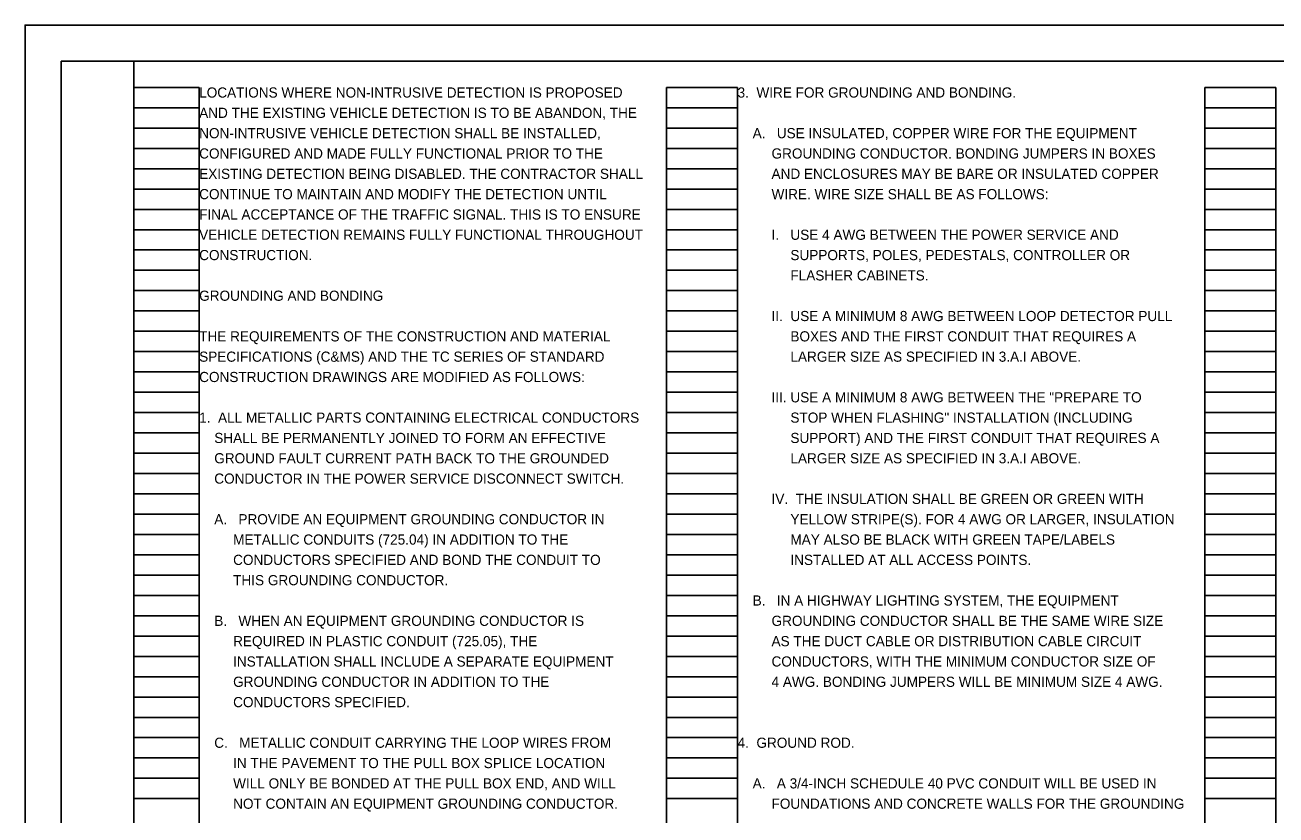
# Model space of a CAD drawing. Extents: x 0 to 44.9, y 0 to 22.
# Drawn here: x 0 to 17.24, y 11.11 to 22 of the extents above; entities that cross this region are included whole.
import ezdxf

# ---------------------------------------------------------------- set-up
doc = ezdxf.new("R2010")
doc.units = 0
for name, color, linetype in [('SH_Border', 7, 'Continuous'), ('SH_Cut_Line', 7, 'Continuous'), ('SH_Data', 7, 'Continuous'), ('SH_Text', 7, 'Continuous')]:
    doc.layers.add(name, color=color, linetype=linetype)

msp = doc.modelspace()

# ---------------------------------------------------------------- linework, layer by layer
at = {"layer": 'SH_Border'}
for points in [[(0.5, 21.5), (1.5, 21.5), (1.5, 0.5), (0.5, 0.5)], [(1.5, 21.5), (33.5, 21.5), (33.5, 0.5), (1.5, 0.5)]]:
    msp.add_lwpolyline(points, close=True, dxfattribs=at)
at = {"layer": 'SH_Cut_Line'}
msp.add_lwpolyline([(0, 0), (34, 0), (34, 22), (0, 22)], close=True, dxfattribs=at)
at = {"layer": 'SH_Data'}
for p, q in [((1.5, 0.98), (1.5, 21.14)), ((1.5, 21.14), (2.4, 21.14)), ((2.4, 0.98), (2.4, 21.14)), ((8.84, 0.98), (8.84, 21.14)), ((8.84, 21.14), (9.82, 21.14)), ((9.82, 0.98), (9.82, 21.14)), ((16.26, 0.98), (16.26, 21.14)), ((16.26, 21.14), (17.24, 21.14)), ((17.24, 0.98), (17.24, 21.14)), ((1.5, 20.86), (2.4, 20.86)), ((8.84, 20.86), (9.82, 20.86)), ((16.26, 20.86), (17.24, 20.86)), ((1.5, 20.58), (2.4, 20.58)), ((8.84, 20.58), (9.82, 20.58)), ((16.26, 20.58), (17.24, 20.58)), ((1.5, 20.3), (2.4, 20.3)), ((8.84, 20.3), (9.82, 20.3)), ((16.26, 20.3), (17.24, 20.3)), ((1.5, 20.02), (2.4, 20.02)), ((8.84, 20.02), (9.82, 20.02)), ((16.26, 20.02), (17.24, 20.02)), ((1.5, 19.74), (2.4, 19.74)), ((8.84, 19.74), (9.82, 19.74)), ((16.26, 19.74), (17.24, 19.74)), ((1.5, 19.46), (2.4, 19.46)), ((8.84, 19.46), (9.82, 19.46)), ((16.26, 19.46), (17.24, 19.46)), ((1.5, 19.18), (2.4, 19.18)), ((8.84, 19.18), (9.82, 19.18)), ((16.26, 19.18), (17.24, 19.18)), ((1.5, 18.9), (2.4, 18.9)), ((8.84, 18.9), (9.82, 18.9)), ((16.26, 18.9), (17.24, 18.9)), ((1.5, 18.62), (2.4, 18.62)), ((8.84, 18.62), (9.82, 18.62)), ((16.26, 18.62), (17.24, 18.62)), ((1.5, 18.34), (2.4, 18.34)), ((8.84, 18.34), (9.82, 18.34)), ((16.26, 18.34), (17.24, 18.34)), ((1.5, 18.06), (2.4, 18.06)), ((8.84, 18.06), (9.82, 18.06)), ((16.26, 18.06), (17.24, 18.06)), ((1.5, 17.78), (2.4, 17.78)), ((8.84, 17.78), (9.82, 17.78)), ((16.26, 17.78), (17.24, 17.78)), ((1.5, 17.5), (2.4, 17.5)), ((8.84, 17.5), (9.82, 17.5)), ((16.26, 17.5), (17.24, 17.5)), ((1.5, 17.22), (2.4, 17.22)), ((8.84, 17.22), (9.82, 17.22)), ((16.26, 17.22), (17.24, 17.22)), ((1.5, 16.94), (2.4, 16.94)), ((8.84, 16.94), (9.82, 16.94)), ((16.26, 16.94), (17.24, 16.94)), ((1.5, 16.66), (2.4, 16.66)), ((8.84, 16.66), (9.82, 16.66)), ((16.26, 16.66), (17.24, 16.66)), ((1.5, 16.38), (2.4, 16.38)), ((8.84, 16.38), (9.82, 16.38)), ((16.26, 16.38), (17.24, 16.38)), ((1.5, 16.1), (2.4, 16.1)), ((8.84, 16.1), (9.82, 16.1)), ((16.26, 16.1), (17.24, 16.1)), ((1.5, 15.82), (2.4, 15.82)), ((8.84, 15.82), (9.82, 15.82)), ((16.26, 15.82), (17.24, 15.82)), ((1.5, 15.54), (2.4, 15.54)), ((8.84, 15.54), (9.82, 15.54)), ((16.26, 15.54), (17.24, 15.54)), ((1.5, 15.26), (2.4, 15.26)), ((8.84, 15.26), (9.82, 15.26)), ((16.26, 15.26), (17.24, 15.26)), ((1.5, 14.98), (2.4, 14.98)), ((8.84, 14.98), (9.82, 14.98)), ((16.26, 14.98), (17.24, 14.98)), ((1.5, 14.7), (2.4, 14.7)), ((8.84, 14.7), (9.82, 14.7)), ((16.26, 14.7), (17.24, 14.7)), ((1.5, 14.42), (2.4, 14.42)), ((8.84, 14.42), (9.82, 14.42)), ((16.26, 14.42), (17.24, 14.42)), ((1.5, 14.14), (2.4, 14.14)), ((8.84, 14.14), (9.82, 14.14)), ((16.26, 14.14), (17.24, 14.14)), ((1.5, 13.86), (2.4, 13.86)), ((8.84, 13.86), (9.82, 13.86)), ((16.26, 13.86), (17.24, 13.86)), ((1.5, 13.58), (2.4, 13.58)), ((8.84, 13.58), (9.82, 13.58)), ((16.26, 13.58), (17.24, 13.58)), ((1.5, 13.3), (2.4, 13.3)), ((8.84, 13.3), (9.82, 13.3)), ((16.26, 13.3), (17.24, 13.3)), ((1.5, 13.02), (2.4, 13.02)), ((8.84, 13.02), (9.82, 13.02)), ((16.26, 13.02), (17.24, 13.02)), ((1.5, 12.74), (2.4, 12.74)), ((8.84, 12.74), (9.82, 12.74)), ((16.26, 12.74), (17.24, 12.74)), ((1.5, 12.46), (2.4, 12.46)), ((8.84, 12.46), (9.82, 12.46)), ((16.26, 12.46), (17.24, 12.46)), ((1.5, 12.18), (2.4, 12.18)), ((8.84, 12.18), (9.82, 12.18)), ((16.26, 12.18), (17.24, 12.18)), ((1.5, 11.9), (2.4, 11.9)), ((8.84, 11.9), (9.82, 11.9)), ((16.26, 11.9), (17.24, 11.9)), ((1.5, 11.62), (2.4, 11.62)), ((8.84, 11.62), (9.82, 11.62)), ((16.26, 11.62), (17.24, 11.62)), ((1.5, 11.34), (2.4, 11.34)), ((8.84, 11.34), (9.82, 11.34)), ((16.26, 11.34), (17.24, 11.34))]:
    msp.add_line(p, q, dxfattribs=at)

# ---------------------------------------------------------------- texts
at = {"layer": 'SH_Text'}
for s, p in [('LOCATIONS WHERE NON-INTRUSIVE DETECTION IS PROPOSED', (2.4, 21)), ('3.  WIRE FOR GROUNDING AND BONDING.', (9.82, 21)), ('AND THE EXISTING VEHICLE DETECTION IS TO BE ABANDON, THE', (2.4, 20.72)), ('NON-INTRUSIVE VEHICLE DETECTION SHALL BE INSTALLED,', (2.4, 20.44)), ('    A.   USE INSULATED, COPPER WIRE FOR THE EQUIPMENT', (9.82, 20.44)), ('CONFIGURED AND MADE FULLY FUNCTIONAL PRIOR TO THE', (2.4, 20.16)), ('         GROUNDING CONDUCTOR. BONDING JUMPERS IN BOXES', (9.82, 20.16)), ('EXISTING DETECTION BEING DISABLED. THE CONTRACTOR SHALL', (2.4, 19.88)), ('         AND ENCLOSURES MAY BE BARE OR INSULATED COPPER', (9.82, 19.88)), ('CONTINUE TO MAINTAIN AND MODIFY THE DETECTION UNTIL', (2.4, 19.6)), ('         WIRE. WIRE SIZE SHALL BE AS FOLLOWS:', (9.82, 19.6)), ('FINAL ACCEPTANCE OF THE TRAFFIC SIGNAL. THIS IS TO ENSURE', (2.4, 19.32)), ('VEHICLE DETECTION REMAINS FULLY FUNCTIONAL THROUGHOUT', (2.4, 19.04)), ('         I.   USE 4 AWG BETWEEN THE POWER SERVICE AND', (9.82, 19.04)), ('CONSTRUCTION.', (2.4, 18.76)), ('              SUPPORTS, POLES, PEDESTALS, CONTROLLER OR', (9.82, 18.76)), ('              FLASHER CABINETS.', (9.82, 18.48)), ('GROUNDING AND BONDING', (2.4, 18.2)), ('         II.  USE A MINIMUM 8 AWG BETWEEN LOOP DETECTOR PULL', (9.82, 17.92)), ('THE REQUIREMENTS OF THE CONSTRUCTION AND MATERIAL', (2.4, 17.64)), ('              BOXES AND THE FIRST CONDUIT THAT REQUIRES A', (9.82, 17.64)), ('SPECIFICATIONS (C&MS) AND THE TC SERIES OF STANDARD', (2.4, 17.36)), ('              LARGER SIZE AS SPECIFIED IN 3.A.I ABOVE.', (9.82, 17.36)), ('CONSTRUCTION DRAWINGS ARE MODIFIED AS FOLLOWS:', (2.4, 17.08)), ('         III. USE A MINIMUM 8 AWG BETWEEN THE "PREPARE TO', (9.82, 16.8)), ('1.  ALL METALLIC PARTS CONTAINING ELECTRICAL CONDUCTORS', (2.4, 16.52)), ('              STOP WHEN FLASHING" INSTALLATION (INCLUDING', (9.82, 16.52)), ('    SHALL BE PERMANENTLY JOINED TO FORM AN EFFECTIVE', (2.4, 16.24)), ('              SUPPORT) AND THE FIRST CONDUIT THAT REQUIRES A', (9.82, 16.24)), ('    GROUND FAULT CURRENT PATH BACK TO THE GROUNDED', (2.4, 15.96)), ('              LARGER SIZE AS SPECIFIED IN 3.A.I ABOVE.', (9.82, 15.96)), ('    CONDUCTOR IN THE POWER SERVICE DISCONNECT SWITCH.', (2.4, 15.68)), ('         IV.  THE INSULATION SHALL BE GREEN OR GREEN WITH', (9.82, 15.4)), ('    A.   PROVIDE AN EQUIPMENT GROUNDING CONDUCTOR IN', (2.4, 15.12)), ('              YELLOW STRIPE(S). FOR 4 AWG OR LARGER, INSULATION', (9.82, 15.12)), ('         METALLIC CONDUITS (725.04) IN ADDITION TO THE', (2.4, 14.84)), ('              MAY ALSO BE BLACK WITH GREEN TAPE/LABELS', (9.82, 14.84)), ('         CONDUCTORS SPECIFIED AND BOND THE CONDUIT TO', (2.4, 14.56)), ('              INSTALLED AT ALL ACCESS POINTS.', (9.82, 14.56)), ('         THIS GROUNDING CONDUCTOR.', (2.4, 14.28)), ('    B.   IN A HIGHWAY LIGHTING SYSTEM, THE EQUIPMENT', (9.82, 14)), ('    B.   WHEN AN EQUIPMENT GROUNDING CONDUCTOR IS', (2.4, 13.72)), ('         GROUNDING CONDUCTOR SHALL BE THE SAME WIRE SIZE', (9.82, 13.72)), ('         REQUIRED IN PLASTIC CONDUIT (725.05), THE', (2.4, 13.44)), ('         AS THE DUCT CABLE OR DISTRIBUTION CABLE CIRCUIT', (9.82, 13.44)), ('         INSTALLATION SHALL INCLUDE A SEPARATE EQUIPMENT', (2.4, 13.16)), ('         CONDUCTORS, WITH THE MINIMUM CONDUCTOR SIZE OF', (9.82, 13.16)), ('         GROUNDING CONDUCTOR IN ADDITION TO THE', (2.4, 12.88)), ('         4 AWG. BONDING JUMPERS WILL BE MINIMUM SIZE 4 AWG.', (9.82, 12.88)), ('         CONDUCTORS SPECIFIED.', (2.4, 12.6)), ('    C.   METALLIC CONDUIT CARRYING THE LOOP WIRES FROM', (2.4, 12.04)), ('4.  GROUND ROD.', (9.82, 12.04)), ('         IN THE PAVEMENT TO THE PULL BOX SPLICE LOCATION', (2.4, 11.76)), ('         WILL ONLY BE BONDED AT THE PULL BOX END, AND WILL', (2.4, 11.48)), ('    A.   A 3/4-INCH SCHEDULE 40 PVC CONDUIT WILL BE USED IN', (9.82, 11.48)), ('         NOT CONTAIN AN EQUIPMENT GROUNDING CONDUCTOR.', (2.4, 11.2)), ('         FOUNDATIONS AND CONCRETE WALLS FOR THE GROUNDING', (9.82, 11.2))]:
    msp.add_text(s, height=0.14, dxfattribs=at).set_placement(p)

doc.saveas('drawing.dxf')
